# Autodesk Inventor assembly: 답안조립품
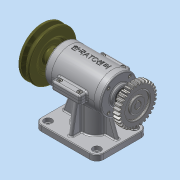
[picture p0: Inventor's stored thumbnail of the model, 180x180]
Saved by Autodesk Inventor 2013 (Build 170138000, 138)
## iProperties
Created: 2015-09
Part Number: 답안조립품
Document SubType Name: Assembly
Designer: dgall
Mass: 2249.07 g
Surface Area: 1628.2 cm^2
Volume: 528.248 cm^3
Density: 4.2576 g/cm^3
Author: dgall
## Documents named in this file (17)
- C:\Users\dgall\Desktop\350907V1037\답안조립품.iam
- C:\Users\dgall\Desktop\350907V1037\본체.ipt
- C:\Users\dgall\Desktop\350907V1037\본체 커버.ipt
- C:\Users\dgall\Desktop\350907V1037\베어링 6201.ipt
- C:\Users\dgall\Desktop\350907V1037\앞커버.ipt
- C:\Users\dgall\Desktop\350907V1037\오일실.ipt
- C:\Users\dgall\Desktop\350907V1037\뒤커버.ipt
- C:\Users\dgall\Desktop\350907V1037\베어링 6202.ipt
- C:\Users\dgall\Desktop\350907V1037\M3x0.5x8.ipt
- C:\Users\dgall\Desktop\350907V1037\편심축.ipt
- C:\Users\dgall\Desktop\350907V1037\키4x4.ipt
- C:\Users\dgall\Desktop\350907V1037\멈춤나사.ipt
- C:\Users\dgall\Desktop\350907V1037\V-벨트풀리.ipt
- C:\Users\dgall\Desktop\350907V1037\스퍼기어.ipt
- C:\Users\dgall\Desktop\350907V1037\M4x0.5x14.ipt
- C:\Users\dgall\Desktop\350907V1037\슬라이드.ipt
- C:\Users\dgall\Desktop\350907V1037\가변스프링.ipt
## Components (14 placed, 4 different names)
1. M3x0.5x8:1
2. M3x0.5x8:2
3. M3x0.5x8:3
4. M3x0.5x8:4
5. M3x0.5x8:5
6. M3x0.5x8:6
7. M3x0.5x8:7
8. M3x0.5x8:8
9. V-벨트풀리:1
10. M4x0.5x14:1
11. M4x0.5x14:2
12. M4x0.5x14:3
13. M4x0.5x14:4
14. 가변스프링:1
